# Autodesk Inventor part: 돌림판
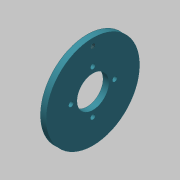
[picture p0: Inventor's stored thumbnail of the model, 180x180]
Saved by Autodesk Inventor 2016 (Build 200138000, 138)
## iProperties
Created: 2019-10
Part Number: 돌림판
Material: 스테인리스강
Document SubType Name: Modeling
Designer: mduedu
Density: 1 g/cm^3
Appearance: 커뎃 파란색
Author: mduedu
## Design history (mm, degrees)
sketch "스케치1" dims "d3" = 30
  geometry: C1 r 32 at (0, 0); C2 r 11 at (0, 0); C3 r 1.7 at (15, 0); C4 r 1.7 at (0, 15); C5 r 1.7 at (-15, 0); C6 r 1.7 at (0, -15); 2 further points
  constraints: 6 centre point, 3 coincident, 2 horizontal alignment, 11 other
  dimensions: "d0" = 64 diameter of C1; "d2" = 3.4 diameter of C3; "d4" = 22 diameter of C2; "d7" = 360 deg dimension on point (0, 0) C3.centre (derived)
extrude "돌출1" new body sketch "스케치1" distance "d9" = 4; taper "d10" = 0 deg
sketch "스케치2" dims "d11" = 54
  geometry: 3 further points
  constraints: 2 vertical alignment, 1 coincident, 2 other
hole "구멍1" sketch "스케치2" at (0, 27) diameter "d13" = 3.242; stored, may be unused: countersink angle "d17" = 90 deg, drill point angle "d19" = 118 deg; dims "d14" = 6, "d15" = 4, "d16" = 2, "d18" = 8
node "솔리드1"
